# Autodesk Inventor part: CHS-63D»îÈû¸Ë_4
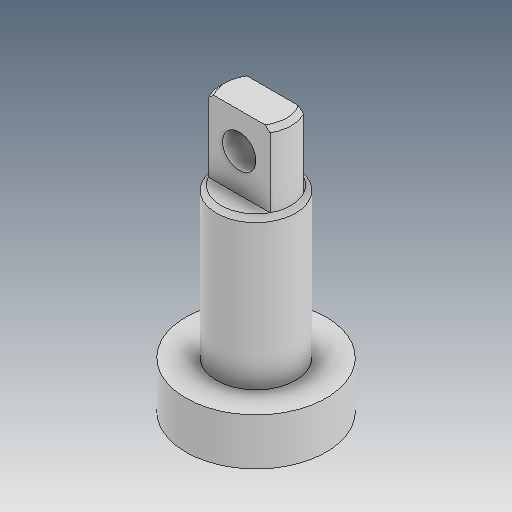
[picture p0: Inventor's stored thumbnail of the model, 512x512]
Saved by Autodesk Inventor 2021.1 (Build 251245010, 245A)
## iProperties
Created: 2019-05
Part Number: CHS-63D»îÈû¸Ë_4
Material: Ogólny
Document SubType Name: Modeling
Designer: user
Density: 1 g/cm^3
Appearance: Domyślna
Author: user
Revision Number: ÈÎºÎ
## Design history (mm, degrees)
feature "ÊäÈë1"
feature "ÊäÈë2"
node "Bryła1"
node "Bryła2"
